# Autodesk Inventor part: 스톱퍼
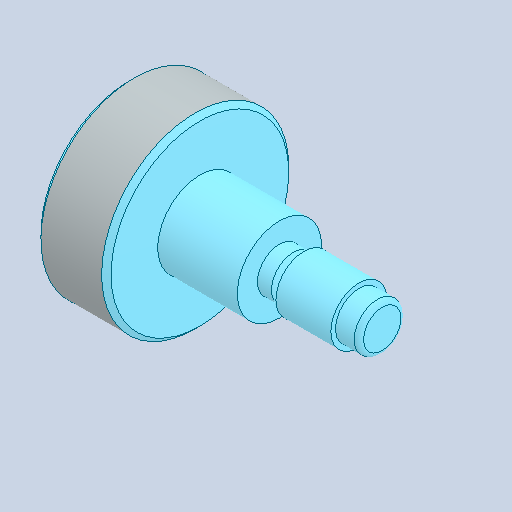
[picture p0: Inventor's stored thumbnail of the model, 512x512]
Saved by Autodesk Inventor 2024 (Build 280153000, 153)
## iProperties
Created: 2024-08
Part Number: 스톱퍼
Material: 강철, 탄소
Document SubType Name: Modeling
Designer: user
Density: 7.85 g/cm^3
Appearance: 기본값
Author: jhkim
Sending System: Autodesk Inventor 2025
Preprocessor: ST-DEVELOPER v20
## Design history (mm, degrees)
feature "솔리드1"
node "솔리드2"
